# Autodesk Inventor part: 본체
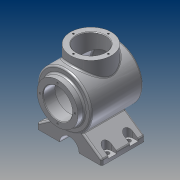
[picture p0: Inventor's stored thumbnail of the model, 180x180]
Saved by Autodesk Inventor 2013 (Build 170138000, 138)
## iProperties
Created: 2017-04
Part Number: 본체
Material: 알루미늄 6061
Document SubType Name: Modeling
Designer: Administrator
Density: 2.71 g/cm^3
Mass: 1670.75 g
Surface Area: 1066.86 cm^2
Volume: 616.514 cm^3
Author: Administrator
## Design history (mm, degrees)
sketch "스케치1"
  geometry: L1 (82, 62)-(82, -58); L2 (109, 62)-(120, 62); L3 (120, 62)-(120, 53); L4 (123, 50)-(129, 50); L5 (132, 47)-(132, -44.454); L6 (109, 62)-(109, 40); L7 (109, 40)-(119, 40); L8 (122, 37)-(122, -37.903); A1 r 113 centre (82, 55) between (82, -58) and (130.282, -47.166); A2 r 103 centre (82, 55) between (82, -48) and (120.11, -40.69); A3 r 3 centre (123, 53) between (120, 53) and (123, 50); A4 r 3 centre (129, 47) between (132, 47) and (129, 50); A5 r 3 centre (119, 37) between (122, 37) and (119, 40); A6 r 3 centre (119, -37.903) between (120.11, -40.69) and (122, -37.903); A7 r 3 centre (129, -44.454) between (130.282, -47.166) and (132, -44.454); 4 further points
  constraints: 16 end point, 16 point on circle, 10 tangent, 7 centre point, 6 point on line, 3 parallel, 3 perpendicular, 2 vertical, 1 horizontal alignment
  dimensions: "d0" = 120 distance of L1.end L1.start; "d3" = 82 distance from line of L1 point (0, 0); "d4" = 54 diameter of L6 L1; "d5" = 76 diameter of L3 L1; "d7" = 12 distance of L2.end point (120, 50); "d8" = 100 diameter of L5 L1; "d9" = 22 distance of L2.start L6.end; "d10" = 10 distance between parallel lines of L5 L8; "d11" = 113 radius of A1; "d12" = 10 radial gap between concentric circles of A1 A2; "d13" = 3 radius of A3; "d14" = 3 radius of A4; "d15" = 3 radius of A5; "d16" = 3 radius of A6; "d17" = 3 radius of A7; "d33" = 50 vertical distance of point (0, 0) L4.start
revolve "회전1" sketch "스케치1" stored, may be unused: angle "d18" = 90 deg
sketch "스케치2"
  geometry: L1 (60, 0)-(60, 10); L2 (60, 10)-(21.584, 36.899); L3 (-60, 0)-(-60, 10); L4 (-60, 10)-(-21.584, 36.899); L5 (18, 0)-(60, 0); L6 (-60, 0)-(-18, 0); A1 r 50 centre (0, 82) between (21.584, 36.899) and (-21.584, 36.899) reference; A2 r 18 centre (0, 0) between (18, 0) and (-18, 0); 2 further points
  constraints: 12 end point, 5 equal length, 4 point on circle, 2 coincident, 1 centre point, 1 horizontal, 1 perpendicular
  dimensions: "d23" = 36 diameter of A2; "d26" = 60 distance of L3.start point (0, 0); "d27" = 120 distance of L1.start L3.start; "d28" = 10 distance of L3.start L3.end; "d29" = 55 deg angle of L3 L4; "d30" = 82 vertical distance of A1.centre L3.start
extrude "돌출1" join sketch "스케치2" stored distance "d31" = 80; taper "d32" = 0 deg
node "작업 평면1"
sketch "스케치3"
  geometry: C1 r 38 at (0, 0); 1 further point
  constraints: 1 centre point, 1 coincident
  dimensions: "d35" = 76 diameter of C1
extrude "돌출2" join sketch "스케치3" stored distance "d36" = 80; taper "d37" = 0 deg
hole "구멍1" diameter "d40" = 54; stored, may be unused: countersink angle "d44" = 90 deg, drill point angle "d46" = 118 deg; dims "d38" = 10, "d39" = 10, "d41" = 6, "d42" = 4, "d43" = 2, "d45" = 8
sketch "스케치4"
  geometry: C1 r 38 at (0, 0) reference; 2 further points
  constraints: 1 vertical alignment
  dimensions: "d47" = 32.5 distance of point (0, 32.5) C1.centre
hole "구멍2" sketch "스케치4" at (0, 32.5) diameter "d48" = 3.242; stored, may be unused: countersink angle "d52" = 90 deg, drill point angle "d54" = 118 deg; dims "d49" = 8, "d50" = 4, "d51" = 2, "d53" = 10
sketch "스케치5"
  geometry: C1 r 27 at (0, 0) reference; 1 further point
  constraints: 1 vertical alignment
  dimensions: "d58" = 32.5 distance of point (0, 32.5) C1.centre
hole "구멍3" sketch "스케치5" at (0, 32.5) diameter "d59" = 3.242; stored, may be unused: countersink angle "d63" = 90 deg, drill point angle "d65" = 118 deg; dims "d60" = 8, "d61" = 4, "d62" = 2, "d64" = 10
node "작업 평면2"
sketch "스케치7"
  geometry: L1 (-60, -72)-(-60, -82) reference; C1 r 47 at (0, 0) reference; 2 further points
  constraints: 1 coincident, 1 other
feature "엠보싱1" sketch "스케치7" dims "d0" = 120, "d3" = 82, "d4" = 54, "d5" = 76, "d7" = 12, "d8" = 100, "d9" = 22, "d10" = 10, "d11" = 113, "d12" = 10, "d13" = 3, "d14" = 3, "d15" = 3, "d16" = 3, "d17" = 3, "d33" = 50, "d69" = 0.5, "d70" = 0
fillet "모깎기1" dims "d71" = 3
chamfer "모따기1" distance "d72" = 1; stored, may be unused: second distance "d73" = 2, angle "d74" = 45 deg
fillet "모깎기2" dims "d75" = 3
fillet "모깎기3" dims "d76" = 3
fillet "모깎기4" dims "d77" = 3
sketch "스케치8"
  geometry: C1 r 4 at (32, 20); 3 further points
  constraints: 1 centre point
  dimensions: "d78" = 8 diameter of C1; "d82" = 10 horizontal distance of point (42, 3) C1.centre; "d83" = 20 vertical distance of C1.centre point (39, 0)
extrude "돌출3" cut sketch "스케치8" distance "d84" = 6; taper "d85" = 0 deg
sketch "스케치9"
  geometry: L1 (10, 57)-(10, -17) reference; L2 (10, 8)-(0, 8); L3 (0, -8)-(10, -8); C1 r 4 at (0, 0) reference; A1 r 8 centre (0, 0) between (0, 8) and (0, -8); 1 further point
  constraints: 4 end point, 2 perpendicular, 2 point on circle, 2 point on line, 2 tangent, 1 centre point, 1 coincident
  dimensions: "d86" = 8 radius of A1
extrude "돌출5" cut sketch "스케치9" stored distance "d90" = 6; taper "d91" = 0 deg
node "솔리드1"
pattern_circular "원형 패턴1" dims angle "d56" = 360 deg
pattern_circular "원형 패턴2" dims angle "d67" = 360 deg
mirror "대칭1"
mirror "대칭2"
other parameters: "d34" = 147, "d98" = 0.5, "d99" = 2, "d100" = 0
